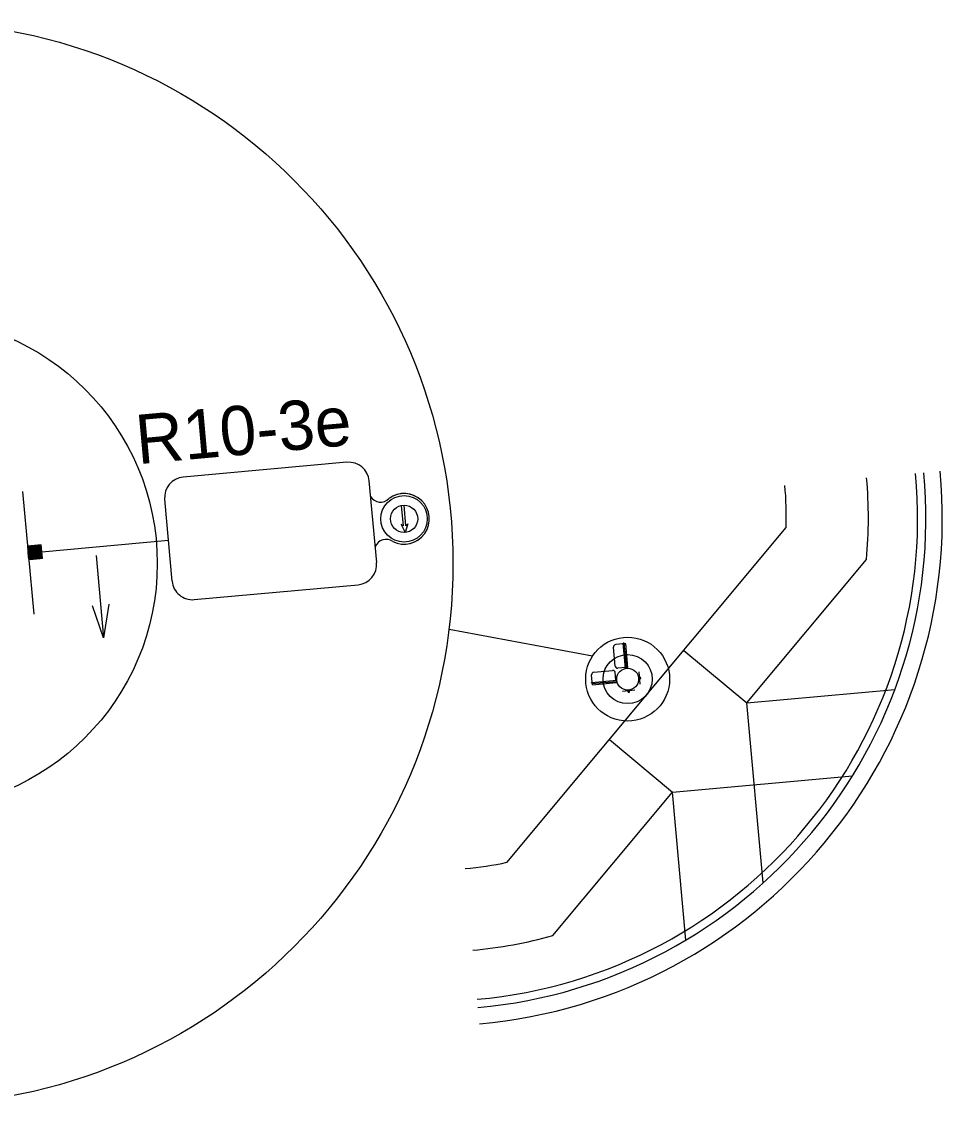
# Model space of a CAD drawing. Extents: x 1277218 to 1279252, y 196860 to 197529.
# Drawn here: x 1279025.6 to 1279111.4, y 197191.1 to 197292.1 of the extents above; entities that cross this region are included whole.
import ezdxf

# ---------------------------------------------------------------- set-up
doc = ezdxf.new("R2010")
doc.units = 0
doc.layers.add('S_EDGE_PAVEMENT', color=7, linetype='Continuous')

msp = doc.modelspace()

# ---------------------------------------------------------------- linework, layer by layer
at = {"layer": 'S_EDGE_PAVEMENT'}
for p, q in [((1279055.94, 197251.05), (1279040.68, 197249.67)), ((1279058.71, 197241.7), (1279058.01, 197249.32)), ((1279025.71, 197248.31), (1279026.75, 197236.88)), ((1279038.94, 197247.59), (1279039.63, 197239.97)), ((1279061.03, 197247.02), (1279061.26, 197247.04)), ((1279061.2, 197245.11), (1279061.03, 197247.02)), ((1279061.43, 197245.13), (1279061.26, 197247.04)), ((1279061, 197245.24), (1279061.37, 197244.5)), ((1279061.2, 197245.11), (1279061, 197245.24)), ((1279061.6, 197245.3), (1279061.37, 197244.5)), ((1279061.6, 197245.3), (1279061.43, 197245.13)), ((1279070.84, 197213.74), (1279096.88, 197244.97)), ((1279027.44, 197243.35), (1279026.17, 197243.23)), ((1279026.18, 197243.13), (1279026.28, 197243.24)), ((1279026.18, 197243.15), (1279026.25, 197243.24)), ((1279026.18, 197243.17), (1279026.23, 197243.24)), ((1279026.18, 197243.19), (1279026.21, 197243.23)), ((1279026.18, 197243.22), (1279026.19, 197243.23)), ((1279026.19, 197243.02), (1279026.38, 197243.25)), ((1279026.19, 197243.04), (1279026.36, 197243.25)), ((1279026.19, 197243.06), (1279026.34, 197243.25)), ((1279026.19, 197243.09), (1279026.32, 197243.24)), ((1279026.19, 197243.11), (1279026.3, 197243.24)), ((1279026.2, 197242.89), (1279026.51, 197243.26)), ((1279026.2, 197242.91), (1279026.49, 197243.26)), ((1279026.2, 197242.94), (1279026.47, 197243.26)), ((1279026.2, 197242.96), (1279026.45, 197243.26)), ((1279026.2, 197242.98), (1279026.43, 197243.25)), ((1279026.2, 197243), (1279026.41, 197243.25)), ((1279026.21, 197242.78), (1279026.62, 197243.27)), ((1279026.21, 197242.81), (1279026.6, 197243.27)), ((1279026.21, 197242.83), (1279026.58, 197243.27)), ((1279026.21, 197242.85), (1279026.56, 197243.27)), ((1279026.21, 197242.87), (1279026.53, 197243.26)), ((1279026.22, 197242.68), (1279026.73, 197243.28)), ((1279026.22, 197242.7), (1279026.71, 197243.28)), ((1279026.22, 197242.72), (1279026.69, 197243.28)), ((1279026.22, 197242.74), (1279026.66, 197243.28)), ((1279026.22, 197242.76), (1279026.64, 197243.27)), ((1279026.23, 197242.57), (1279026.84, 197243.29)), ((1279026.23, 197242.59), (1279026.81, 197243.29)), ((1279026.23, 197242.61), (1279026.79, 197243.29)), ((1279026.23, 197242.63), (1279026.77, 197243.29)), ((1279026.23, 197242.66), (1279026.75, 197243.28)), ((1279026.24, 197242.46), (1279026.94, 197243.3)), ((1279026.24, 197242.48), (1279026.92, 197243.3)), ((1279026.24, 197242.5), (1279026.9, 197243.3)), ((1279026.24, 197242.53), (1279026.88, 197243.3)), ((1279026.24, 197242.55), (1279026.86, 197243.29)), ((1279026.25, 197242.35), (1279027.05, 197243.31)), ((1279026.25, 197242.38), (1279027.03, 197243.31)), ((1279026.25, 197242.4), (1279027.01, 197243.31)), ((1279026.25, 197242.42), (1279026.99, 197243.3)), ((1279026.25, 197242.44), (1279026.97, 197243.3)), ((1279026.26, 197242.25), (1279027.16, 197243.32)), ((1279026.26, 197242.27), (1279027.14, 197243.32)), ((1279026.26, 197242.29), (1279027.12, 197243.32)), ((1279026.26, 197242.31), (1279027.09, 197243.31)), ((1279026.26, 197242.33), (1279027.07, 197243.31)), ((1279026.27, 197242.14), (1279027.27, 197243.33)), ((1279026.27, 197242.16), (1279027.25, 197243.33)), ((1279026.27, 197242.18), (1279027.22, 197243.33)), ((1279026.27, 197242.2), (1279027.2, 197243.32)), ((1279026.27, 197242.22), (1279027.18, 197243.32)), ((1279026.28, 197242.03), (1279027.37, 197243.34)), ((1279026.28, 197242.05), (1279027.35, 197243.34)), ((1279026.28, 197242.07), (1279027.33, 197243.34)), ((1279026.28, 197242.1), (1279027.31, 197243.33)), ((1279026.28, 197242.12), (1279027.29, 197243.33)), ((1279026.29, 197241.97), (1279027.44, 197243.35)), ((1279026.29, 197241.99), (1279027.42, 197243.34)), ((1279026.29, 197242.01), (1279027.4, 197243.34)), ((1279026.31, 197241.96), (1279027.45, 197243.33)), ((1279026.33, 197241.96), (1279027.45, 197243.31)), ((1279026.35, 197241.97), (1279027.45, 197243.29)), ((1279026.37, 197241.97), (1279027.45, 197243.26)), ((1279026.39, 197241.97), (1279027.45, 197243.24)), ((1279026.41, 197241.97), (1279027.46, 197243.22)), ((1279026.44, 197241.97), (1279027.46, 197243.2)), ((1279026.46, 197241.98), (1279027.46, 197243.18)), ((1279026.48, 197241.98), (1279027.46, 197243.16)), ((1279026.5, 197241.98), (1279027.46, 197243.14)), ((1279026.52, 197241.98), (1279027.47, 197243.11)), ((1279026.54, 197241.98), (1279027.47, 197243.09)), ((1279026.57, 197241.99), (1279027.47, 197243.07)), ((1279026.59, 197241.99), (1279027.47, 197243.05)), ((1279026.61, 197241.99), (1279027.47, 197243.03)), ((1279026.63, 197241.99), (1279027.47, 197243.01)), ((1279026.65, 197241.99), (1279027.48, 197242.98)), ((1279026.67, 197242), (1279027.48, 197242.96)), ((1279026.69, 197242), (1279027.48, 197242.94)), ((1279026.72, 197242), (1279027.48, 197242.92)), ((1279026.74, 197242), (1279027.48, 197242.9)), ((1279026.76, 197242), (1279027.49, 197242.88)), ((1279026.78, 197242.01), (1279027.49, 197242.86)), ((1279026.8, 197242.01), (1279027.49, 197242.83)), ((1279027.56, 197242.08), (1279027.44, 197243.35)), ((1279027.5, 197242.71), (1279039.29, 197243.78)), ((1279027.56, 197242.08), (1279026.29, 197241.96)), ((1279026.82, 197242.01), (1279027.49, 197242.81)), ((1279026.85, 197242.01), (1279027.49, 197242.79)), ((1279026.87, 197242.01), (1279027.5, 197242.77)), ((1279026.89, 197242.02), (1279027.5, 197242.75)), ((1279026.91, 197242.02), (1279027.5, 197242.73)), ((1279026.93, 197242.02), (1279027.5, 197242.7)), ((1279026.95, 197242.02), (1279027.5, 197242.68)), ((1279026.97, 197242.02), (1279027.51, 197242.66)), ((1279027, 197242.03), (1279027.51, 197242.64)), ((1279027.02, 197242.03), (1279027.51, 197242.62)), ((1279027.04, 197242.03), (1279027.51, 197242.6)), ((1279027.06, 197242.03), (1279027.51, 197242.57)), ((1279027.08, 197242.03), (1279027.52, 197242.55)), ((1279027.1, 197242.04), (1279027.52, 197242.53)), ((1279027.13, 197242.04), (1279027.52, 197242.51)), ((1279027.15, 197242.04), (1279027.52, 197242.49)), ((1279027.17, 197242.04), (1279027.52, 197242.47)), ((1279027.19, 197242.04), (1279027.53, 197242.45)), ((1279027.21, 197242.05), (1279027.53, 197242.42)), ((1279027.23, 197242.05), (1279027.53, 197242.4)), ((1279027.25, 197242.05), (1279027.53, 197242.38)), ((1279027.28, 197242.05), (1279027.53, 197242.36)), ((1279027.3, 197242.05), (1279027.54, 197242.34)), ((1279027.32, 197242.05), (1279027.54, 197242.32)), ((1279027.34, 197242.06), (1279027.54, 197242.29)), ((1279027.36, 197242.06), (1279027.54, 197242.27)), ((1279027.38, 197242.06), (1279027.54, 197242.25)), ((1279027.41, 197242.06), (1279027.55, 197242.23)), ((1279027.43, 197242.06), (1279027.55, 197242.21)), ((1279027.45, 197242.07), (1279027.55, 197242.19)), ((1279027.47, 197242.07), (1279027.55, 197242.17)), ((1279027.49, 197242.07), (1279027.55, 197242.14)), ((1279027.51, 197242.07), (1279027.55, 197242.12)), ((1279027.53, 197242.07), (1279027.56, 197242.1)), ((1279027.56, 197242.08), (1279027.56, 197242.08)), ((1279032.57, 197242.35), (1279033.26, 197234.68)), ((1279093.2, 197228.61), (1279104.35, 197241.99)), ((1279041.71, 197238.24), (1279056.97, 197239.62)), ((1279078.84, 197232.97), (1279065.45, 197235.45)), ((1279080.94, 197232.05), (1279080.78, 197233.8)), ((1279081.69, 197234.11), (1279080.99, 197234.05)), ((1279081.79, 197234.19), (1279081.68, 197234.18)), ((1279081.89, 197231.83), (1279081.68, 197234.18)), ((1279082.01, 197231.84), (1279081.79, 197234.19)), ((1279081.92, 197234.13), (1279081.8, 197234.12)), ((1279082.12, 197231.92), (1279081.92, 197234.13)), ((1279087.33, 197233.51), (1279093.2, 197228.61)), ((1279081.89, 197231.9), (1279081.19, 197231.84)), ((1279082.01, 197231.84), (1279081.89, 197231.83)), ((1279082.12, 197231.92), (1279082, 197231.91)), ((1279078.73, 197230.52), (1279081.08, 197230.73)), ((1279078.8, 197230.53), (1279078.74, 197231.23)), ((1279078.95, 197231.47), (1279080.7, 197231.63)), ((1279081.01, 197230.73), (1279080.95, 197231.43)), ((1279081.09, 197230.62), (1279081.08, 197230.73)), ((1279083.14, 197231.5), (1279083.24, 197230.35)), ((1279083.31, 197231), (1279083.19, 197230.99)), ((1279083.19, 197230.89), (1279083.29, 197231)), ((1279083.19, 197230.89), (1279083.28, 197231)), ((1279083.19, 197230.89), (1279083.28, 197231)), ((1279083.19, 197230.89), (1279083.28, 197231)), ((1279083.19, 197230.9), (1279083.28, 197231)), ((1279083.19, 197230.9), (1279083.28, 197231)), ((1279083.19, 197230.9), (1279083.27, 197231)), ((1279083.19, 197230.9), (1279083.27, 197231)), ((1279083.19, 197230.9), (1279083.27, 197231)), ((1279083.19, 197230.91), (1279083.27, 197231)), ((1279083.19, 197230.91), (1279083.26, 197231)), ((1279083.19, 197230.91), (1279083.26, 197231)), ((1279083.19, 197230.91), (1279083.26, 197230.99)), ((1279083.19, 197230.92), (1279083.26, 197230.99)), ((1279083.19, 197230.92), (1279083.26, 197230.99)), ((1279083.19, 197230.92), (1279083.25, 197230.99)), ((1279083.19, 197230.92), (1279083.25, 197230.99)), ((1279083.19, 197230.92), (1279083.25, 197230.99)), ((1279083.19, 197230.93), (1279083.25, 197230.99)), ((1279083.19, 197230.93), (1279083.25, 197230.99)), ((1279083.19, 197230.93), (1279083.24, 197230.99)), ((1279083.19, 197230.93), (1279083.24, 197230.99)), ((1279083.19, 197230.93), (1279083.24, 197230.99)), ((1279083.19, 197230.94), (1279083.24, 197230.99)), ((1279083.19, 197230.94), (1279083.23, 197230.99)), ((1279083.19, 197230.94), (1279083.23, 197230.99)), ((1279083.19, 197230.94), (1279083.23, 197230.99)), ((1279083.19, 197230.95), (1279083.23, 197230.99)), ((1279083.19, 197230.95), (1279083.23, 197230.99)), ((1279083.19, 197230.95), (1279083.22, 197230.99)), ((1279083.19, 197230.95), (1279083.22, 197230.99)), ((1279083.19, 197230.95), (1279083.22, 197230.99)), ((1279083.19, 197230.96), (1279083.22, 197230.99)), ((1279083.19, 197230.96), (1279083.22, 197230.99)), ((1279083.19, 197230.96), (1279083.21, 197230.99)), ((1279083.19, 197230.96), (1279083.21, 197230.99)), ((1279083.19, 197230.97), (1279083.21, 197230.99)), ((1279083.19, 197230.97), (1279083.21, 197230.99)), ((1279083.19, 197230.97), (1279083.2, 197230.99)), ((1279083.19, 197230.97), (1279083.2, 197230.99)), ((1279083.19, 197230.97), (1279083.2, 197230.99)), ((1279083.19, 197230.98), (1279083.2, 197230.99)), ((1279083.19, 197230.98), (1279083.2, 197230.99)), ((1279083.19, 197230.98), (1279083.19, 197230.99)), ((1279083.19, 197230.98), (1279083.19, 197230.99)), ((1279083.19, 197230.98), (1279083.19, 197230.99)), ((1279083.19, 197230.99), (1279083.19, 197230.99)), ((1279083.2, 197230.86), (1279083.31, 197231)), ((1279083.2, 197230.86), (1279083.31, 197231)), ((1279083.2, 197230.86), (1279083.31, 197231)), ((1279083.2, 197230.86), (1279083.31, 197231)), ((1279083.2, 197230.87), (1279083.31, 197231)), ((1279083.2, 197230.87), (1279083.31, 197231)), ((1279083.2, 197230.87), (1279083.3, 197231)), ((1279083.2, 197230.87), (1279083.3, 197231)), ((1279083.2, 197230.87), (1279083.3, 197231)), ((1279083.2, 197230.88), (1279083.3, 197231)), ((1279083.2, 197230.88), (1279083.3, 197231)), ((1279083.2, 197230.88), (1279083.29, 197231)), ((1279083.2, 197230.88), (1279083.29, 197231)), ((1279083.2, 197230.89), (1279083.29, 197231)), ((1279083.2, 197230.86), (1279083.31, 197230.99)), ((1279083.32, 197230.87), (1279083.2, 197230.86)), ((1279083.21, 197230.86), (1279083.31, 197230.99)), ((1279083.21, 197230.86), (1279083.31, 197230.99)), ((1279083.21, 197230.86), (1279083.31, 197230.99)), ((1279083.21, 197230.86), (1279083.31, 197230.99)), ((1279083.21, 197230.86), (1279083.31, 197230.98)), ((1279083.22, 197230.86), (1279083.31, 197230.98)), ((1279083.22, 197230.86), (1279083.31, 197230.98)), ((1279083.22, 197230.86), (1279083.31, 197230.98)), ((1279083.22, 197230.86), (1279083.32, 197230.97)), ((1279083.22, 197230.86), (1279083.32, 197230.97)), ((1279083.23, 197230.86), (1279083.32, 197230.97)), ((1279083.23, 197230.86), (1279083.32, 197230.97)), ((1279083.23, 197230.86), (1279083.32, 197230.97)), ((1279083.23, 197230.86), (1279083.32, 197230.96)), ((1279083.24, 197230.87), (1279083.32, 197230.96)), ((1279083.24, 197230.86), (1279083.32, 197230.96)), ((1279083.24, 197230.86), (1279083.32, 197230.96)), ((1279083.24, 197230.87), (1279083.32, 197230.95)), ((1279083.24, 197230.87), (1279083.32, 197230.95)), ((1279083.25, 197230.87), (1279083.32, 197230.95)), ((1279083.25, 197230.87), (1279083.32, 197230.95)), ((1279083.25, 197230.87), (1279083.32, 197230.95)), ((1279083.25, 197230.87), (1279083.32, 197230.94)), ((1279083.26, 197230.87), (1279083.32, 197230.94)), ((1279083.26, 197230.87), (1279083.32, 197230.94)), ((1279083.26, 197230.87), (1279083.32, 197230.94)), ((1279083.26, 197230.87), (1279083.32, 197230.94)), ((1279083.26, 197230.87), (1279083.32, 197230.93)), ((1279083.27, 197230.87), (1279083.32, 197230.93)), ((1279083.27, 197230.87), (1279083.32, 197230.93)), ((1279083.27, 197230.87), (1279083.32, 197230.93)), ((1279083.27, 197230.87), (1279083.32, 197230.92)), ((1279083.27, 197230.87), (1279083.32, 197230.92)), ((1279083.28, 197230.87), (1279083.32, 197230.92)), ((1279083.28, 197230.87), (1279083.32, 197230.92)), ((1279083.28, 197230.87), (1279083.32, 197230.92)), ((1279083.28, 197230.87), (1279083.32, 197230.91)), ((1279083.29, 197230.87), (1279083.32, 197230.91)), ((1279083.29, 197230.87), (1279083.32, 197230.91)), ((1279083.29, 197230.87), (1279083.32, 197230.91)), ((1279083.29, 197230.87), (1279083.32, 197230.91)), ((1279083.29, 197230.87), (1279083.32, 197230.9)), ((1279083.3, 197230.87), (1279083.32, 197230.9)), ((1279083.3, 197230.87), (1279083.32, 197230.9)), ((1279083.3, 197230.87), (1279083.32, 197230.9)), ((1279083.3, 197230.87), (1279083.32, 197230.89)), ((1279083.3, 197230.87), (1279083.32, 197230.89)), ((1279083.32, 197230.87), (1279083.31, 197231)), ((1279083.31, 197230.87), (1279083.32, 197230.89)), ((1279083.31, 197230.87), (1279083.32, 197230.89)), ((1279083.31, 197230.87), (1279083.32, 197230.89)), ((1279083.31, 197230.87), (1279083.32, 197230.88)), ((1279083.32, 197230.87), (1279083.32, 197230.88)), ((1279083.32, 197230.87), (1279083.32, 197230.88)), ((1279083.32, 197230.87), (1279083.32, 197230.88)), ((1279083.32, 197230.87), (1279083.32, 197230.88)), ((1279083.32, 197230.87), (1279083.32, 197230.87)), ((1279078.75, 197230.41), (1279078.73, 197230.52)), ((1279078.75, 197230.41), (1279081.09, 197230.62)), ((1279078.83, 197230.3), (1279078.81, 197230.41)), ((1279078.83, 197230.3), (1279081.03, 197230.5)), ((1279081.03, 197230.5), (1279081.02, 197230.61)), ((1279082.77, 197229.79), (1279081.63, 197229.68)), ((1279082.14, 197229.62), (1279082.24, 197229.74)), ((1279082.14, 197229.62), (1279082.24, 197229.74)), ((1279082.14, 197229.62), (1279082.24, 197229.74)), ((1279082.14, 197229.63), (1279082.24, 197229.74)), ((1279082.14, 197229.63), (1279082.24, 197229.74)), ((1279082.14, 197229.63), (1279082.23, 197229.74)), ((1279082.14, 197229.63), (1279082.23, 197229.74)), ((1279082.14, 197229.63), (1279082.23, 197229.74)), ((1279082.14, 197229.64), (1279082.23, 197229.74)), ((1279082.14, 197229.64), (1279082.22, 197229.74)), ((1279082.14, 197229.64), (1279082.22, 197229.74)), ((1279082.14, 197229.64), (1279082.22, 197229.74)), ((1279082.14, 197229.64), (1279082.22, 197229.74)), ((1279082.14, 197229.65), (1279082.22, 197229.74)), ((1279082.14, 197229.65), (1279082.21, 197229.74)), ((1279082.15, 197229.6), (1279082.14, 197229.73)), ((1279082.14, 197229.65), (1279082.21, 197229.73)), ((1279082.14, 197229.65), (1279082.21, 197229.73)), ((1279082.14, 197229.66), (1279082.21, 197229.73)), ((1279082.14, 197229.66), (1279082.21, 197229.73)), ((1279082.14, 197229.66), (1279082.2, 197229.73)), ((1279082.14, 197229.66), (1279082.2, 197229.73)), ((1279082.14, 197229.66), (1279082.2, 197229.73)), ((1279082.14, 197229.67), (1279082.2, 197229.73)), ((1279082.14, 197229.67), (1279082.19, 197229.73)), ((1279082.14, 197229.67), (1279082.19, 197229.73)), ((1279082.14, 197229.67), (1279082.19, 197229.73)), ((1279082.14, 197229.68), (1279082.19, 197229.73)), ((1279082.14, 197229.68), (1279082.19, 197229.73)), ((1279082.14, 197229.68), (1279082.18, 197229.73)), ((1279082.14, 197229.68), (1279082.18, 197229.73)), ((1279082.14, 197229.68), (1279082.18, 197229.73)), ((1279082.14, 197229.69), (1279082.18, 197229.73)), ((1279082.14, 197229.69), (1279082.17, 197229.73)), ((1279082.14, 197229.69), (1279082.17, 197229.73)), ((1279082.14, 197229.69), (1279082.17, 197229.73)), ((1279082.14, 197229.69), (1279082.17, 197229.73)), ((1279082.14, 197229.7), (1279082.17, 197229.73)), ((1279082.14, 197229.7), (1279082.16, 197229.73)), ((1279082.14, 197229.7), (1279082.16, 197229.73)), ((1279082.14, 197229.7), (1279082.16, 197229.73)), ((1279082.14, 197229.71), (1279082.16, 197229.73)), ((1279082.14, 197229.71), (1279082.16, 197229.73)), ((1279082.14, 197229.71), (1279082.15, 197229.73)), ((1279082.14, 197229.71), (1279082.15, 197229.73)), ((1279082.14, 197229.71), (1279082.15, 197229.73)), ((1279082.14, 197229.72), (1279082.15, 197229.73)), ((1279082.14, 197229.72), (1279082.14, 197229.73)), ((1279082.14, 197229.72), (1279082.14, 197229.73)), ((1279082.14, 197229.72), (1279082.14, 197229.73)), ((1279082.14, 197229.72), (1279082.14, 197229.73)), ((1279082.14, 197229.73), (1279082.14, 197229.73)), ((1279082.15, 197229.6), (1279082.26, 197229.74)), ((1279082.15, 197229.6), (1279082.26, 197229.74)), ((1279082.15, 197229.6), (1279082.26, 197229.74)), ((1279082.15, 197229.6), (1279082.26, 197229.74)), ((1279082.15, 197229.61), (1279082.26, 197229.74)), ((1279082.15, 197229.61), (1279082.25, 197229.74)), ((1279082.15, 197229.61), (1279082.25, 197229.74)), ((1279082.15, 197229.61), (1279082.25, 197229.74)), ((1279082.15, 197229.61), (1279082.25, 197229.74)), ((1279082.15, 197229.62), (1279082.25, 197229.74)), ((1279082.15, 197229.6), (1279082.26, 197229.73)), ((1279082.15, 197229.6), (1279082.26, 197229.73)), ((1279082.16, 197229.6), (1279082.26, 197229.73)), ((1279082.16, 197229.6), (1279082.26, 197229.73)), ((1279082.16, 197229.6), (1279082.26, 197229.73)), ((1279082.16, 197229.6), (1279082.26, 197229.72)), ((1279082.17, 197229.6), (1279082.26, 197229.72)), ((1279082.17, 197229.6), (1279082.26, 197229.72)), ((1279082.17, 197229.6), (1279082.26, 197229.72)), ((1279082.17, 197229.6), (1279082.26, 197229.71)), ((1279082.17, 197229.6), (1279082.26, 197229.71)), ((1279082.18, 197229.6), (1279082.27, 197229.71)), ((1279082.18, 197229.6), (1279082.26, 197229.71)), ((1279082.18, 197229.6), (1279082.26, 197229.71)), ((1279082.18, 197229.6), (1279082.27, 197229.7)), ((1279082.18, 197229.6), (1279082.27, 197229.7)), ((1279082.19, 197229.6), (1279082.27, 197229.7)), ((1279082.27, 197229.61), (1279082.26, 197229.74)), ((1279093.2, 197228.61), (1279107, 197229.86)), ((1279082.15, 197229.6), (1279082.27, 197229.61)), ((1279082.19, 197229.6), (1279082.27, 197229.7)), ((1279082.19, 197229.6), (1279082.27, 197229.7)), ((1279082.19, 197229.61), (1279082.27, 197229.69)), ((1279082.2, 197229.61), (1279082.27, 197229.69)), ((1279082.2, 197229.61), (1279082.27, 197229.69)), ((1279082.2, 197229.61), (1279082.27, 197229.69)), ((1279082.2, 197229.61), (1279082.27, 197229.68)), ((1279082.2, 197229.61), (1279082.27, 197229.68)), ((1279082.21, 197229.61), (1279082.27, 197229.68)), ((1279082.21, 197229.61), (1279082.27, 197229.68)), ((1279082.21, 197229.61), (1279082.27, 197229.68)), ((1279082.21, 197229.61), (1279082.27, 197229.67)), ((1279082.21, 197229.61), (1279082.27, 197229.67)), ((1279082.22, 197229.61), (1279082.27, 197229.67)), ((1279082.22, 197229.61), (1279082.27, 197229.67)), ((1279082.22, 197229.61), (1279082.27, 197229.66)), ((1279082.22, 197229.61), (1279082.27, 197229.66)), ((1279082.23, 197229.61), (1279082.27, 197229.66)), ((1279082.23, 197229.61), (1279082.27, 197229.66)), ((1279082.23, 197229.61), (1279082.27, 197229.66)), ((1279082.23, 197229.61), (1279082.27, 197229.65)), ((1279082.23, 197229.61), (1279082.27, 197229.65)), ((1279082.24, 197229.61), (1279082.27, 197229.65)), ((1279082.24, 197229.61), (1279082.27, 197229.65)), ((1279082.24, 197229.61), (1279082.27, 197229.65)), ((1279082.24, 197229.61), (1279082.27, 197229.64)), ((1279082.24, 197229.61), (1279082.27, 197229.64)), ((1279082.25, 197229.61), (1279082.27, 197229.64)), ((1279082.25, 197229.61), (1279082.27, 197229.64)), ((1279082.25, 197229.61), (1279082.27, 197229.63)), ((1279082.25, 197229.61), (1279082.27, 197229.63)), ((1279082.26, 197229.61), (1279082.27, 197229.63)), ((1279082.26, 197229.61), (1279082.27, 197229.63)), ((1279082.26, 197229.61), (1279082.27, 197229.63)), ((1279082.26, 197229.61), (1279082.27, 197229.62)), ((1279082.26, 197229.61), (1279082.27, 197229.62)), ((1279082.27, 197229.61), (1279082.27, 197229.62)), ((1279082.27, 197229.61), (1279082.27, 197229.62)), ((1279082.27, 197229.61), (1279082.27, 197229.62)), ((1279082.27, 197229.61), (1279082.27, 197229.61)), ((1279094.72, 197211.82), (1279093.2, 197228.61)), ((1279080.4, 197225.2), (1279086.27, 197220.3)), ((1279086.27, 197220.3), (1279103.07, 197221.82)), ((1279075.12, 197206.93), (1279086.27, 197220.3)), ((1279087.52, 197206.5), (1279086.27, 197220.3))]:
    msp.add_line(p, q, dxfattribs=at)
msp.add_lwpolyline([(1279033.75, 197237.8), (1279033.26, 197234.68), (1279032.23, 197237.66)], dxfattribs=at)
for centre, radius in [((1279015.31, 197241.61), 50.51), ((1279015.31, 197241.61), 22.95), ((1279061.26, 197245.77), 2.17), ((1279061.26, 197245.77), 1.27), ((1279082.1, 197230.83), 3.91), ((1279082.1, 197230.83), 2.29), ((1279082.1, 197230.83), 1.02)]:
    msp.add_circle(centre, radius, dxfattribs=at)
for centre, radius, start, end in [((1279056.11, 197249.14), 1.91, 5.1779, 95.1779), ((1279064, 197245.92), 45.13, 275.1779, 5.1779), ((1279064, 197245.92), 45.9, 275.1779, 5.1779), ((1279064, 197245.92), 47.43, 275.1779, 5.1779), ((1279040.85, 197247.76), 1.91, 95.1779, 185.1779), ((1279064, 197245.92), 40.54, 354.4382, 5.1779), ((1279061.26, 197245.77), 2.36, 243.9181, 126.4377), ((1279061.26, 197245.77), 2.36, 47.6845, 126.4377), ((1279064, 197245.92), 32.89, 358.352, 5.1779), ((1279059.07, 197248.4), 1.07, 210.3735, 316.9807), ((1279059.58, 197242.79), 1.07, 53.3751, 159.9823), ((1279061.26, 197245.77), 2.36, 243.9181, 322.6712), ((1279056.8, 197241.53), 1.91, 275.1779, 5.1779), ((1279041.54, 197240.14), 1.91, 185.1779, 275.1779), ((1279081.01, 197233.82), 0.229, 95.1779, 185.1779), ((1279081.17, 197232.07), 0.229, 185.1779, 275.1779), ((1279078.97, 197231.25), 0.229, 95.1779, 185.1779), ((1279080.72, 197231.4), 0.229, 5.1779, 95.1779), ((1279064, 197245.92), 32.89, 275.1779, 282.0038), ((1279064, 197245.92), 40.54, 275.1779, 285.9176)]:
    msp.add_arc(centre, radius, start, end, dxfattribs=at)

# ---------------------------------------------------------------- texts
msp.add_text('R10-3e', height=4.59, rotation=5.1779, dxfattribs=at).set_placement((1279036.46, 197250.86))

doc.saveas('drawing.dxf')
